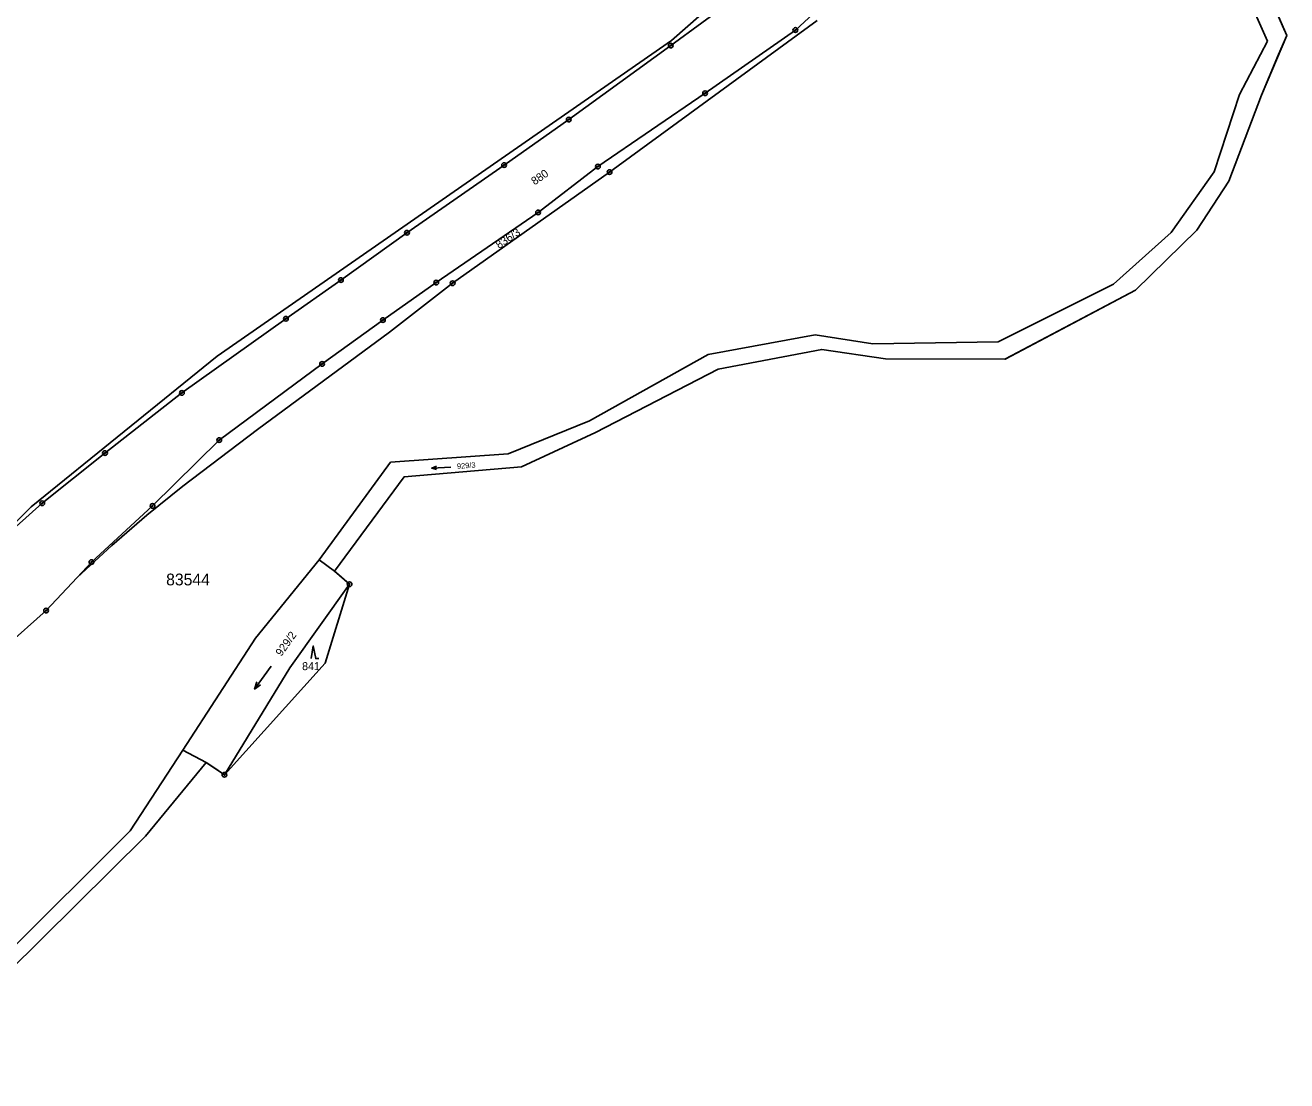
# Model space of a CAD drawing. Extents: x -547623 to -538651, y -1096714 to -1086522.
# Drawn here: x -543480.3 to -543212.3, y -1088755.9 to -1088531.7 of the extents above; entities that cross this region are included whole.
import ezdxf

# ---------------------------------------------------------------- set-up
doc = ezdxf.new("R2010")
doc.units = 0
for name, color, linetype in [('podzemní_provozovana', 7, 'Continuous'), ('Vrstva 1', 7, 'Continuous'), ('Vrstva 25', 7, 'Continuous'), ('Vrstva 41', 7, 'Continuous'), ('Vrstva 52', 7, 'Continuous'), ('Vrstva 53', 7, 'Continuous'), ('Vrstva 83', 7, 'Continuous'), ('Vrstva 86', 7, 'Continuous')]:
    doc.layers.add(name, color=color, linetype=linetype)

msp = doc.modelspace()

# ---------------------------------------------------------------- linework, layer by layer
at = {"layer": 'Vrstva 1'}
for p, q in [((-543356.14, -1088562.91), (-543312.01, -1088530.71)), ((-543389.47, -1088586.53), (-543356.14, -1088562.91)), ((-543402.87, -1088596.95), (-543389.47, -1088586.53)), ((-543430.92, -1088617.61), (-543402.87, -1088596.95)), ((-543446.78, -1088629.64), (-543430.92, -1088617.61)), ((-543454.46, -1088635.8), (-543446.78, -1088629.64)), ((-543461.88, -1088642.25), (-543454.46, -1088635.8)), ((-543469.25, -1088649.01), (-543461.88, -1088642.25)), ((-543469.25, -1088649.01), (-543466.22, -1088645.77)), ((-543475.84, -1088656.06), (-543469.25, -1088649.01)), ((-543484.36, -1088663.66), (-543475.84, -1088656.06))]:
    msp.add_line(p, q, dxfattribs=at)
for points in [[(-543299.75, -1088517.1), (-543316.67, -1088532.74)], [(-543323.38, -1088521.48), (-543343.15, -1088536.04)], [(-543221.5, -1088523.44), (-543216.34, -1088535.11)], [(-543316.67, -1088532.74), (-543335.83, -1088546.18)], [(-543343.15, -1088536.04), (-543364.8, -1088551.76)], [(-543216.34, -1088535.11), (-543222.31, -1088546.47)], [(-543335.83, -1088546.18), (-543358.62, -1088561.74)], [(-543222.31, -1088546.47), (-543227.66, -1088562.84)], [(-543364.8, -1088551.76), (-543378.53, -1088561.44)], [(-543378.53, -1088561.44), (-543399.17, -1088575.8)], [(-543358.62, -1088561.74), (-543371.32, -1088571.5)], [(-543227.66, -1088562.84), (-543236.84, -1088575.76)], [(-543371.32, -1088571.5), (-543392.96, -1088586.4)], [(-543399.17, -1088575.8), (-543413.2, -1088585.85)], [(-543236.84, -1088575.76), (-543249.06, -1088586.71)], [(-543413.2, -1088585.85), (-543424.9, -1088594.07)], [(-543392.96, -1088586.4), (-543404.29, -1088594.35)], [(-543249.06, -1088586.71), (-543273.6, -1088599)], [(-543424.9, -1088594.07), (-543446.99, -1088609.84)], [(-543404.29, -1088594.35), (-543417.2, -1088603.67)], [(-543312.46, -1088597.49), (-543335.19, -1088601.7)], [(-543300.21, -1088599.38), (-543312.46, -1088597.49)], [(-543273.6, -1088599), (-543300.21, -1088599.38)], [(-543335.19, -1088601.7), (-543360.37, -1088615.76)], [(-543417.2, -1088603.67), (-543439.07, -1088619.85)], [(-543446.99, -1088609.84), (-543463.33, -1088622.61)], [(-543360.37, -1088615.76), (-543377.66, -1088622.79)], [(-543439.07, -1088619.85), (-543453.22, -1088633.82)], [(-543463.33, -1088622.61), (-543476.67, -1088633.25)], [(-543402.67, -1088624.55), (-543417.82, -1088645.26)], [(-543377.66, -1088622.79), (-543402.67, -1088624.55)], [(-543476.67, -1088633.25), (-543488.51, -1088643.79)], [(-543453.22, -1088633.82), (-543466.22, -1088645.77)], [(-543417.82, -1088645.26), (-543431.37, -1088661.9)], [(-543417.82, -1088645.26), (-543414.57, -1088647.68)], [(-543424.07, -1088668.24), (-543411.37, -1088650.47)], [(-543431.37, -1088661.9), (-543446.77, -1088685.71)], [(-543437.96, -1088690.95), (-543424.07, -1088668.24)], [(-543446.77, -1088685.71), (-543457.97, -1088702.86)], [(-543446.77, -1088685.71), (-543441.82, -1088688.32)], [(-543457.97, -1088702.86), (-543511.31, -1088755.94)]]:
    msp.add_lwpolyline(points, dxfattribs=at)
at = {"layer": 'Vrstva 25'}
for points in [[(-543393.91, -1088625.81), (-543392.92, -1088625.42)], [(-543389.89, -1088625.59), (-543393.91, -1088625.81), (-543392.89, -1088626.09)], [(-543419.55, -1088666.25), (-543419.08, -1088663.57), (-543418.54, -1088666.25), (-543417.87, -1088666.25)], [(-543428.04, -1088667.88), (-543431.54, -1088672.74), (-543430.26, -1088671.82)], [(-543431.54, -1088672.74), (-543431.07, -1088671.23)]]:
    msp.add_lwpolyline(points, dxfattribs=at)
at = {"layer": 'Vrstva 41'}
for points in [[(-543212.27, -1088533.91), (-543217.52, -1088521.87)], [(-543217.67, -1088546.61), (-543212.27, -1088533.91)], [(-543224.57, -1088564.86), (-543217.67, -1088546.61)], [(-543231.36, -1088575.26), (-543224.57, -1088564.86)], [(-543244.44, -1088588.02), (-543231.36, -1088575.26)], [(-543272.08, -1088602.64), (-543244.44, -1088588.02)], [(-543333.08, -1088604.76), (-543311.07, -1088600.6)], [(-543311.07, -1088600.6), (-543297.51, -1088602.57)], [(-543297.51, -1088602.57), (-543272.08, -1088602.64)], [(-543359.13, -1088618.23), (-543333.08, -1088604.76)], [(-543374.82, -1088625.54), (-543359.13, -1088618.23)], [(-543399.79, -1088627.67), (-543374.82, -1088625.54)], [(-543414.57, -1088647.68), (-543399.79, -1088627.67)], [(-543411.37, -1088650.47), (-543414.57, -1088647.68)], [(-543416.53, -1088667.22), (-543411.37, -1088650.47)], [(-543437.96, -1088690.95), (-543416.53, -1088667.22)], [(-543454.73, -1088704.01), (-543441.82, -1088688.32)], [(-543441.82, -1088688.32), (-543437.96, -1088690.95)], [(-543484.01, -1088733.04), (-543454.73, -1088704.01)]]:
    msp.add_lwpolyline(points, dxfattribs=at)
at = {"layer": 'Vrstva 52'}
for points in [[(-543317.5, -1088512.5), (-543343, -1088535), (-543439.5, -1088602), (-543479, -1088634), (-543564, -1088719.5)], [(-543217.52, -1088521.87), (-543213.18, -1088531.83), (-543212.27, -1088533.91), (-543214, -1088537.97), (-543217.67, -1088546.61), (-543224.57, -1088564.86), (-543231.36, -1088575.26), (-543244.44, -1088588.02), (-543272.01, -1088602.6), (-543272.08, -1088602.64), (-543272.13, -1088602.64), (-543297.51, -1088602.57), (-543311.07, -1088600.6), (-543333.08, -1088604.76), (-543359.13, -1088618.23), (-543374.82, -1088625.54), (-543399.79, -1088627.67), (-543414.57, -1088647.68), (-543413.65, -1088648.48), (-543411.37, -1088650.47), (-543416.53, -1088667.22), (-543437.96, -1088690.95), (-543440.41, -1088689.28), (-543441.82, -1088688.32), (-543454.73, -1088704.01), (-543484.01, -1088733.04)]]:
    msp.add_lwpolyline(points, dxfattribs=at)
at = {"layer": 'Vrstva 83'}
for centre, radius in [((-543316.67, -1088532.74), 0.5), ((-543316.67, -1088532.74), 0.1), ((-543343.15, -1088536.04), 0.5), ((-543343.15, -1088536.04), 0.1), ((-543335.83, -1088546.18), 0.5), ((-543335.83, -1088546.18), 0.1), ((-543364.8, -1088551.76), 0.5), ((-543364.8, -1088551.76), 0.1), ((-543378.53, -1088561.44), 0.5), ((-543378.53, -1088561.44), 0.1), ((-543358.62, -1088561.74), 0.5), ((-543358.62, -1088561.74), 0.1), ((-543356.14, -1088562.91), 0.5), ((-543356.14, -1088562.91), 0.1), ((-543371.32, -1088571.5), 0.5), ((-543371.32, -1088571.5), 0.1), ((-543399.17, -1088575.8), 0.5), ((-543399.17, -1088575.8), 0.1), ((-543413.2, -1088585.85), 0.5), ((-543413.2, -1088585.85), 0.1), ((-543392.96, -1088586.4), 0.5), ((-543392.96, -1088586.4), 0.1), ((-543389.47, -1088586.53), 0.5), ((-543389.47, -1088586.53), 0.1), ((-543424.9, -1088594.07), 0.5), ((-543424.9, -1088594.07), 0.1), ((-543404.29, -1088594.35), 0.5), ((-543404.29, -1088594.35), 0.1), ((-543417.2, -1088603.67), 0.5), ((-543417.2, -1088603.67), 0.1), ((-543446.99, -1088609.84), 0.5), ((-543446.99, -1088609.84), 0.1), ((-543439.07, -1088619.85), 0.5), ((-543439.07, -1088619.85), 0.1), ((-543463.33, -1088622.61), 0.5), ((-543463.33, -1088622.61), 0.1), ((-543476.67, -1088633.25), 0.5), ((-543476.67, -1088633.25), 0.1), ((-543453.22, -1088633.82), 0.5), ((-543453.22, -1088633.82), 0.1), ((-543466.22, -1088645.77), 0.5), ((-543466.22, -1088645.77), 0.1), ((-543411.37, -1088650.47), 0.5), ((-543411.37, -1088650.47), 0.1), ((-543475.84, -1088656.06), 0.5), ((-543475.84, -1088656.06), 0.1), ((-543437.96, -1088690.95), 0.5), ((-543437.96, -1088690.95), 0.1)]:
    msp.add_circle(centre, radius, dxfattribs=at)

# ---------------------------------------------------------------- texts
at = {"layer": 'podzemní_provozovana'}
for s, height, rotation, p in [('880', 1.7, 34.5553, (-543372.06, -1088565.76)), ('929/3', 1.14, 4.5986, (-543388.51, -1088625.98))]:
    msp.add_text(s, height=height, rotation=rotation, dxfattribs=at).set_placement(p)
at = {"layer": 'Vrstva 53'}
msp.add_text('83544', height=2.5, dxfattribs=at).set_placement((-543450.34, -1088650.71))
at = {"layer": 'Vrstva 86'}
for s, rotation, p in [('836/3', 34.2, (-543379.62, -1088579.29)), ('929/2', 54.4232, (-543425.86, -1088665.9))]:
    msp.add_text(s, height=1.7, rotation=rotation, dxfattribs=at).set_placement(p)
msp.add_text('841', height=1.7, dxfattribs=at).set_placement((-543421.46, -1088668.72))

doc.saveas('drawing.dxf')
